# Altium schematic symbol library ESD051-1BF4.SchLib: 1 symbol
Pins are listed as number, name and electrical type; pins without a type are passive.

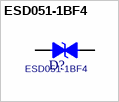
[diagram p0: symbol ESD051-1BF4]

## ESD051-1BF4
designator D?
footprint ST_0201B
pins: 1, 2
